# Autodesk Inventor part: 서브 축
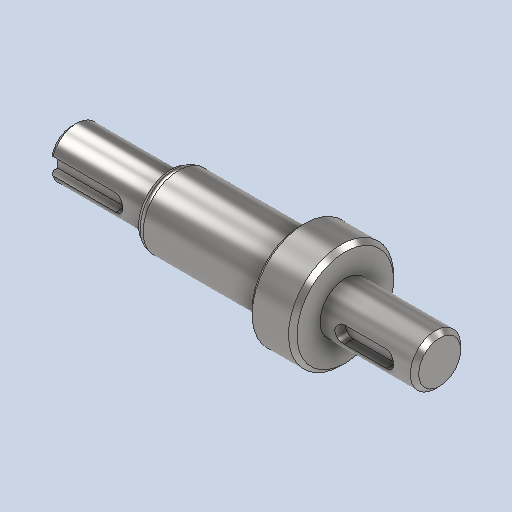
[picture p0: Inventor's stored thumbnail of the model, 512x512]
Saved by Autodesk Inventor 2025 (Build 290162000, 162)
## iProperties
Created: 2024-07
Part Number: 서브 축
Material: 강철, 연강
Document SubType Name: Modeling
Designer: SAMSUNG
Density: 7.86 g/cm^3
Appearance: 기본값
Author: jhkim
Revision Number: 1
Sending System: Autodesk Inventor 2025
Preprocessor: ST-DEVELOPER v20
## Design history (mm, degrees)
feature "솔리드1"
node "솔리드2"
